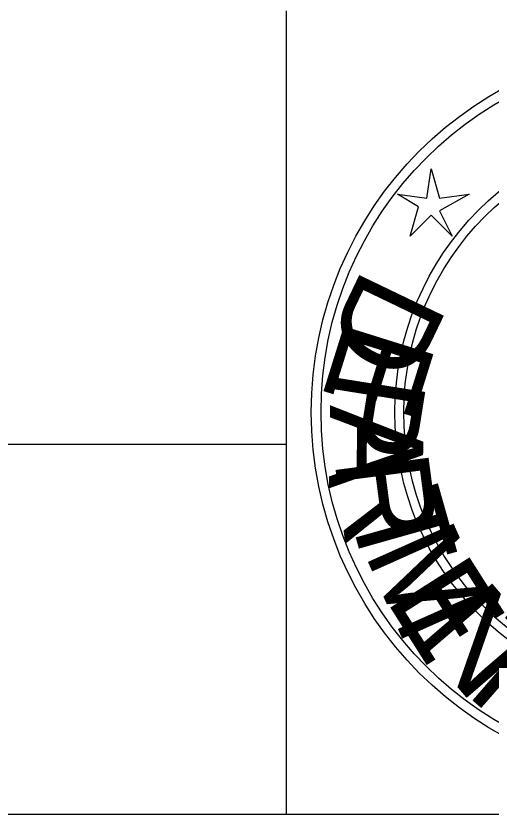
# Model space of a CAD drawing. Extents: x -12822 to 16384, y -6351 to 1913.
# Drawn here: x 36.23 to 65.86, y -4825.34 to -4775.62 of the extents above; entities that cross this region are included whole.
import ezdxf

# ---------------------------------------------------------------- set-up
doc = ezdxf.new("R2010")
doc.units = 0
doc.layers.add('great seal', color=7, linetype='Continuous')
doc.layers.add('SHT-BNDRY', color=7, linetype='Continuous')

msp = doc.modelspace()

# ---------------------------------------------------------------- linework, layer by layer
at = {"layer": 'great seal'}
msp.add_lwpolyline([(62.124, -4785.137), (62.65, -4786.977), (64.489, -4786.714), (62.65, -4787.765), (63.438, -4789.342), (62.124, -4788.028), (60.81, -4789.342), (61.336, -4787.502), (60.022, -4786.714), (61.862, -4786.977)], close=True, dxfattribs=at)
msp.add_lwpolyline([(62.124, -4785.137), (62.65, -4786.977), (64.489, -4786.714), (62.65, -4787.765), (63.438, -4789.342), (62.124, -4788.028), (60.81, -4789.342), (61.336, -4787.502), (60.022, -4786.714), (61.862, -4786.977)], close=True, dxfattribs=at)
msp.add_lwpolyline([(62.124, -4785.137), (62.65, -4786.977), (64.489, -4786.714), (62.65, -4787.765), (63.438, -4789.342), (62.124, -4788.028), (60.81, -4789.342), (61.336, -4787.502), (60.022, -4786.714), (61.862, -4786.977)], close=True, dxfattribs=at)
for radius in [22.994, 22.994, 22.994, 22.389, 22.389, 22.389, 17.779, 17.779, 17.779, 17.222, 17.222, 17.222]:
    msp.add_circle((77.645, -4800.299), radius, dxfattribs=at)
at = {"layer": 'SHT-BNDRY'}
for p, q in [((53.098, -4825.343), (53.098, -4775.293)), ((-725.039, -4802.293), (53.098, -4802.293))]:
    msp.add_line(p, q, dxfattribs=at)
msp.add_lwpolyline([(-787.524, -4825.343), (824.976, -4825.343), (824.976, -3775.343), (-787.524, -3775.343)], close=True, dxfattribs=at)

# ---------------------------------------------------------------- texts
at = {"layer": 'great seal'}
for s, rotation, p in [('D', 244.3352, (57.92, -4791.181)), ('D', 244.3352, (57.92, -4791.181)), ('D', 244.3352, (57.92, -4791.181)), ('E', 252.6236, (56.869, -4794.334)), ('E', 252.6236, (56.869, -4794.334)), ('E', 252.6236, (56.869, -4794.334)), ('P', 260.912, (56.081, -4797.487)), ('P', 260.912, (56.081, -4797.487)), ('P', 260.912, (56.081, -4797.487)), ('A', 269.2004, (55.818, -4799.852)), ('A', 269.2004, (55.818, -4799.852)), ('A', 269.2004, (55.818, -4799.852)), ('R', 277.4888, (56.081, -4803.268)), ('R', 277.4888, (56.081, -4803.268)), ('R', 277.4888, (56.081, -4803.268)), ('T', 285.7771, (56.869, -4806.159)), ('T', 285.7771, (56.869, -4806.159)), ('T', 285.7771, (56.869, -4806.159)), ('M', 294.0655, (57.92, -4809.049)), ('M', 294.0655, (57.92, -4809.049)), ('M', 294.0655, (57.92, -4809.049)), ('E', 302.3539, (59.234, -4811.939)), ('E', 302.3539, (59.234, -4811.939)), ('E', 302.3539, (59.234, -4811.939)), ('N', 310.6423, (61.073, -4814.304)), ('N', 310.6423, (61.073, -4814.304)), ('N', 310.6423, (61.073, -4814.304)), ('T', 318.9307, (63.175, -4816.932)), ('T', 318.9307, (63.175, -4816.932)), ('T', 318.9307, (63.175, -4816.932))]:
    msp.add_text(s, height=5.851, rotation=rotation, dxfattribs=at).set_placement(p)

doc.saveas('drawing.dxf')
